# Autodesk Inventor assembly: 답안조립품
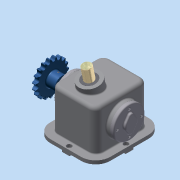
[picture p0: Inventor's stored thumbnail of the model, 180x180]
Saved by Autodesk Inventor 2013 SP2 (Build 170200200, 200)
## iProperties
Created: 2014-11
Part Number: 답안조립품
Document SubType Name: Assembly
Designer: dgall
Author: dgall
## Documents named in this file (13)
- C:\Documents and Settings\dgall\바탕 화면\441122v1006\답안조립품.iam
- C:\Documents and Settings\dgall\바탕 화면\441122v1006\1.본체.ipt
- C:\Documents and Settings\dgall\바탕 화면\441122v1006\뒤커버.ipt
- C:\Documents and Settings\dgall\바탕 화면\441122v1006\앞커버.ipt
- C:\Documents and Settings\dgall\바탕 화면\441122v1006\오일실.ipt
- C:\Documents and Settings\dgall\바탕 화면\441122v1006\베어링 6205.ipt
- C:\Documents and Settings\dgall\바탕 화면\441122v1006\편심축.ipt
- C:\Documents and Settings\dgall\바탕 화면\441122v1006\키 8x8.ipt
- C:\Documents and Settings\dgall\바탕 화면\441122v1006\5-체인 스프로킷.ipt
- C:\Documents and Settings\dgall\바탕 화면\441122v1006\부시.ipt
- C:\Documents and Settings\dgall\바탕 화면\441122v1006\슬라이드.ipt
- C:\Documents and Settings\dgall\바탕 화면\441122v1006\멈춤나사 M5x0.5.ipt
- C:\Documents and Settings\dgall\바탕 화면\441122v1006\M4x0.5.ipt
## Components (10 placed, 3 different names)
1. 1.본체:1
2. 5-체인 스프로킷:1
3. M4x0.5:1
4. M4x0.5:2
5. M4x0.5:3
6. M4x0.5:4
7. M4x0.5:5
8. M4x0.5:6
9. M4x0.5:7
10. M4x0.5:8
